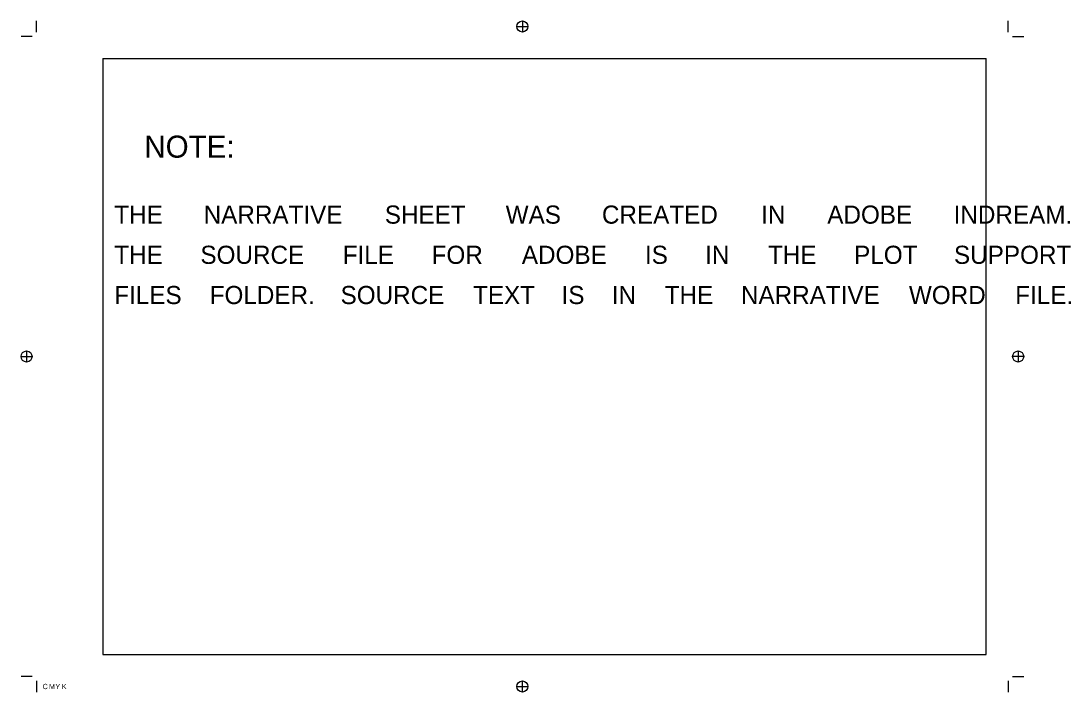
# Model space of a CAD drawing. Extents: x 3093332 to 3098087, y 661840 to 664880.
import ezdxf

# ---------------------------------------------------------------- set-up
doc = ezdxf.new("R2010")
doc.units = 0
for name, color, linetype in [('Default', 7, 'Continuous'), ('G-ANNO-NOTE', 7, 'Continuous'), ('V-ANNO-DIMS', 7, 'Continuous'), ('V-GRID-FRAM', 7, 'Continuous')]:
    doc.layers.add(name, color=color, linetype=linetype)

msp = doc.modelspace()

# ---------------------------------------------------------------- linework, layer by layer
at = {"layer": 'Default'}
msp.add_line((3093702.4, 664710.2), (3097702.4, 664710.2), dxfattribs=at)
at = {"layer": 'V-ANNO-DIMS'}
for p, q in [((3093402.4, 664830.2), (3093402.4, 664880.2)), ((3095602.4, 664880.2), (3095602.4, 664830.2)), ((3097802.4, 664830.2), (3097802.4, 664880.2)), ((3095577.4, 664855.2), (3095627.4, 664855.2)), ((3093382.4, 664810.2), (3093332.4, 664810.2)), ((3097822.4, 664810.2), (3097872.4, 664810.2)), ((3093332.4, 663360.2), (3093382.4, 663360.2)), ((3093357.4, 663385.2), (3093357.4, 663335.2)), ((3097872.4, 663360.2), (3097822.4, 663360.2)), ((3097847.4, 663385.2), (3097847.4, 663335.2)), ((3093382.4, 661910.2), (3093332.4, 661910.2)), ((3093402.4, 661890.2), (3093402.4, 661840.2)), ((3095602.4, 661840.2), (3095602.4, 661890.2)), ((3097802.4, 661890.2), (3097802.4, 661840.2)), ((3097822.4, 661910.2), (3097872.4, 661910.2)), ((3095577.4, 661865.2), (3095627.4, 661865.2))]:
    msp.add_line(p, q, dxfattribs=at)
for centre in [(3095602.4, 664855.2), (3093357.4, 663360.2), (3097847.4, 663360.2), (3095602.4, 661865.2)]:
    msp.add_circle(centre, 25, dxfattribs=at)
at = {"layer": 'V-GRID-FRAM'}
for p, q in [((3093702.4, 664710.2), (3093702.4, 662010.2)), ((3097702.4, 662010.2), (3097702.4, 664710.2)), ((3093702.4, 662010.2), (3097702.4, 662010.2))]:
    msp.add_line(p, q, dxfattribs=at)

# ---------------------------------------------------------------- texts
at = {"layer": 'G-ANNO-NOTE'}
for s, height, p in [('NOTE:', 100, (3093890.8, 664260.9)), ('THE ', 82.14, (3093754.6, 663962)), ('NARRATIVE ', 82.14, (3094159.4, 663962)), ('SHEET ', 82.14, (3094979.6, 663962)), ('WAS ', 82.14, (3095526.9, 663962)), ('CREATED ', 82.14, (3095962.7, 663962)), ('IN ', 82.14, (3096683.6, 663962)), ('ADOBE ', 82.14, (3096983, 663962)), ('INDREAM.', 82.14, (3097555.2, 663962)), ('THE ', 82.14, (3093754.6, 663779.9)), ('SOURCE ', 82.14, (3094144.7, 663779.9)), ('FILE ', 82.14, (3094788.9, 663779.9)), ('FOR ', 82.14, (3095191.5, 663779.9)), ('ADOBE ', 82.14, (3095600.1, 663779.9)), ('IS ', 82.14, (3096157.6, 663779.9)), ('IN ', 82.14, (3096429.9, 663779.9)), ('THE ', 82.14, (3096714.6, 663779.9)), ('PLOT ', 82.14, (3097104.6, 663779.9)), ('SUPPORT ', 82.14, (3097556.7, 663779.9)), ('FILES ', 82.14, (3093754.6, 663597.7)), ('FOLDER. ', 82.14, (3094186.6, 663597.7)), (' SOURCE ', 82.14, (3094748.8, 663597.7)), ('TEXT ', 82.14, (3095379.1, 663597.7)), ('IS ', 82.14, (3095780, 663597.7)), ('IN ', 82.14, (3096007.3, 663597.7)), ('THE ', 82.14, (3096247, 663597.7)), ('NARRATIVE ', 82.14, (3096592.2, 663597.7)), ('WORD ', 82.14, (3097352.7, 663597.7)), ('FILE.', 82.14, (3097834.1, 663597.7))]:
    msp.add_text(s, height=height, dxfattribs=at).set_placement(p)
at = {"layer": 'V-ANNO-DIMS'}
for s, p in [('C', (3093429.9, 661853.3)), ('M', (3093458.9, 661853.3)), ('Y', (3093487.9, 661853.3)), ('K', (3093516.9, 661853.3))]:
    msp.add_text(s, height=23.9, dxfattribs=at).set_placement(p)

doc.saveas('drawing.dxf')
